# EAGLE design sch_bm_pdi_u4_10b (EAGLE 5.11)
AUTHOR: Nigel Batten; DATE: 10th May 2012; PRODUCT: PDIMate XMegaA4U BMP001U4; RANGE: BreadMate; VERSION: Sch1.0b
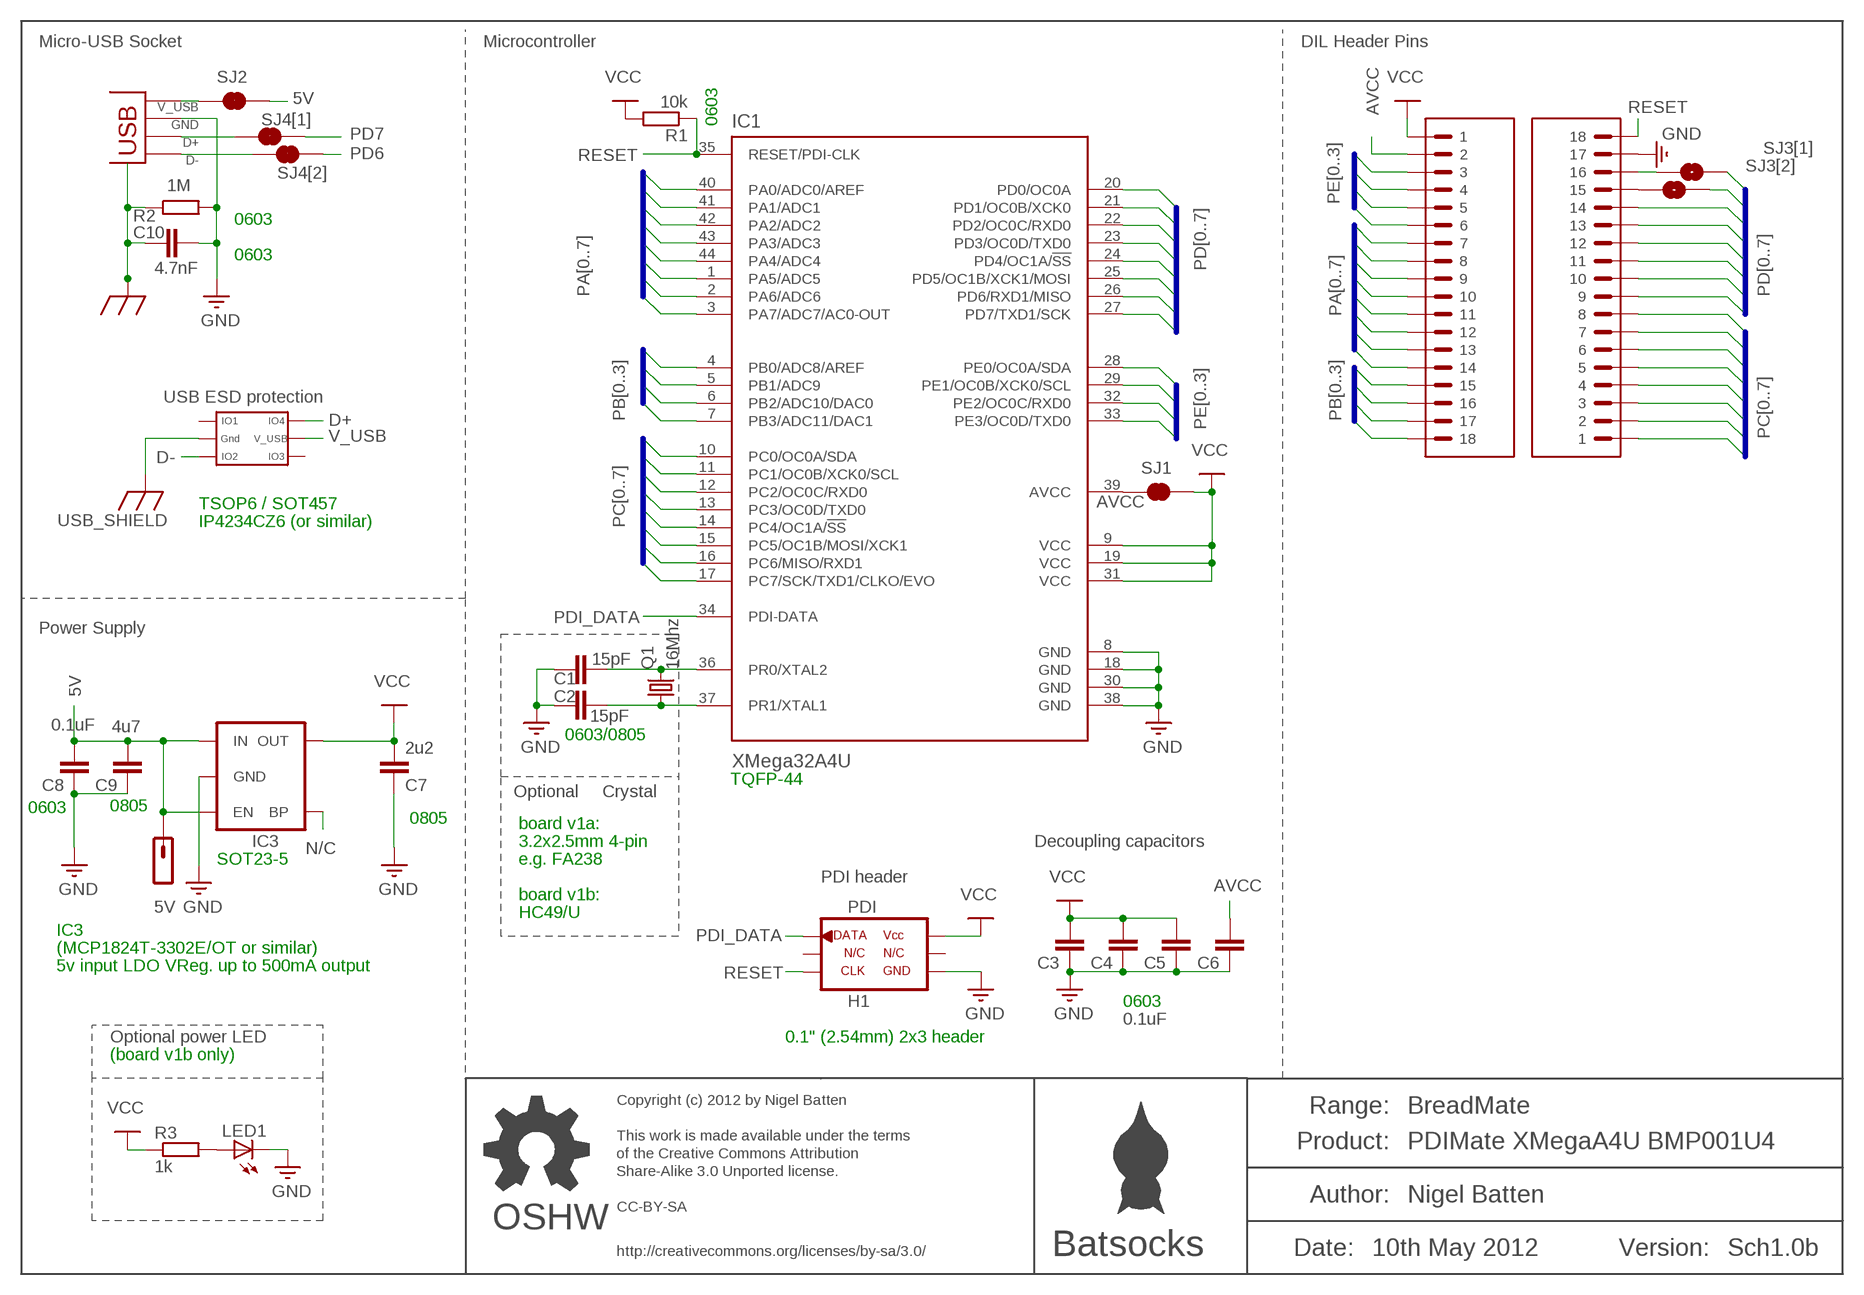
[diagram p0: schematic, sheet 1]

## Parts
5V  M01TEST  [TEST_PAD_1]
C1  15pF  C_EU0805UNMARK  [C0805U]
C2  15pF  C_EU0805UNMARK  [C0805U]
C3  0.1uF  C_EU0603  [C0603]
C4  0.1uF  C_EU0603MARK  [C0603M]
C5  0.1uF  C_EU0603MARK  [C0603M]
C6  0.1uF  C_EU0603MARK  [C0603M]
C7  2u2  C_EU0805MARK  [C0805M]
C8  0.1uF  C_EU0603MARK  [C0603M]
C9  4u7  C_EU0805MARK  [C0805M]
C10  4.7nF  C_EU0603MARK  [C0603M]
H1  PDI  AVR_PDI_6  [AVR_ISP_6]
IC1  XMega32A4U  AT-XMEGA-XXA4-AUMEDIUM  [TQFP44_M]
IC2  USB_ESD  [SOT457]
IC3  LDO  V_REG_LDOSMD  [SOT23-5]
LED1  LED0603_DIODE  [0603_DIODE]
Q1  16Mhz  CRYSTALU  [HC49/S_U]
R1  10k  RESISTOR0603MARK  [R0603M]
R2  1M  RESISTOR0603MARK  [R0603M]
R3  1k  RESISTOR0603UNMARKED  [R0603U]
SJ1  SOLDERJUMPER_NC  [SJ_NC]
SJ2  SOLDERJUMPER_NC  [SJ_NC]
SJ3[1]  SOLDERJUMPER_NOSMALL_UNMARKED  [SJ_NO_SMALL_U]
SJ3[2]  SOLDERJUMPER_NOSMALL_UNMARKED  [SJ_NO_SMALL_U]
SJ4[1]  SOLDERJUMPER_NCSMALL_UNMARKED  [SJ_NC_SMALL_U]
SJ4[2]  SOLDERJUMPER_NCSMALL_UNMARKED  [SJ_NC_SMALL_U]
U$2  HEADER_18BIGPADS_UNMARKED  [HEADER_18_BIGPADS_UNMARKED]
U$3  HEADER_18BIGPADS_UNMARKED  [HEADER_18_BIGPADS_UNMARKED]
U$4  LOGO_BATSOCKSTINY  [LOGO_BATSOCKS_TINY]
U$5  LOGO_OSHWTINY  [LOGO_OSHW_TINY]
USB_SKT  USB_SHIELD_8  [USB_MICRO_B]

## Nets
5V: 5V.P$1 C8.2 C9.2 IC3.1(IN) IC3.3(EN) SJ2.2
AVCC: C6.2 IC1.39(AVCC) SJ1.2 U$2.P$2
D+: IC2.P$6(IO4) SJ4[1].1 USB_SKT.D+
D-: IC2.P$3(IO2) SJ4[2].1 USB_SKT.D-
GND: C1.2 C2.2 C3.1 C4.1 C5.1 C6.1 C7.2 C8.1 C9.1 C10.1 H1.P$6(GND) IC1.8(GND) IC1.18(GND) IC1.30(GND) IC1.38(GND) IC3.2(GND) LED1.K(C) R2.2 U$3.P$17 USB_SKT.GND
N$1: C2.1 IC1.37(PR1/XTAL1) Q1.1
N$2: C1.1 IC1.36(PR0/XTAL2) Q1.2
N$3: SJ3[2].1 U$3.P$15
N$4: SJ3[1].1 U$3.P$16
N$5: LED1.A R3.2
N/C: IC3.4(BP)
PA0: IC1.40(PA0/ADC0/AREF) U$2.P$7
PA1: IC1.41(PA1/ADC1) U$2.P$8
PA2: IC1.42(PA2/ADC2) U$2.P$9
PA3: IC1.43(PA3/ADC3) U$2.P$10
PA4: IC1.44(PA4/ADC4) U$2.P$11
PA5: IC1.1(PA5/ADC5) U$2.P$12
PA6: IC1.2(PA6/ADC6) U$2.P$13
PA7: IC1.3(PA7/ADC7/AC0-OUT) U$2.P$14
PB0: IC1.4(PB0/ADC8/AREF) U$2.P$15
PB1: IC1.5(PB1/ADC9) U$2.P$16
PB2: IC1.6(PB2/ADC10/DAC0) U$2.P$17
PB3: IC1.7(PB3/ADC11/DAC1) U$2.P$18
PC0: IC1.10(PC0/OC0A/SDA) U$3.P$1
PC1: IC1.11(PC1/OC0B/XCK0/SCL) U$3.P$2
PC2: IC1.12(PC2/OC0C/RXD0) U$3.P$3
PC3: IC1.13(PC3/OC0D/TXD0) U$3.P$4
PC4: IC1.14(PC4/OC1A/!SS) U$3.P$5
PC5: IC1.15(PC5/OC1B/MOSI/XCK1) U$3.P$6
PC6: IC1.16(PC6/MISO/RXD1) U$3.P$7
PC7: IC1.17(PC7/SCK/TXD1/CLKO/EVO) U$3.P$8
PD0: IC1.20(PD0/OC0A) U$3.P$9
PD1: IC1.21(PD1/OC0B/XCK0) U$3.P$10
PD2: IC1.22(PD2/OC0C/RXD0) U$3.P$11
PD3: IC1.23(PD3/OC0D/TXD0) U$3.P$12
PD4: IC1.24(PD4/OC1A/!SS) U$3.P$13
PD5: IC1.25(PD5/OC1B/XCK1/MOSI) U$3.P$14
PD6: IC1.26(PD6/RXD1/MISO) SJ3[2].2 SJ4[2].2
PD7: IC1.27(PD7/TXD1/SCK) SJ3[1].2 SJ4[1].2
PDI_DATA: H1.P$1(DATA) IC1.34(PDI-DATA)
PE0: IC1.28(PE0/OC0A/SDA) U$2.P$3
PE1: IC1.29(PE1/OC0B/XCK0/SCL) U$2.P$4
PE2: IC1.32(PE2/OC0C/RXD0) U$2.P$5
PE3: IC1.33(PE3/OC0D/TXD0) U$2.P$6
RESET: H1.P$5(CLK) IC1.35(RESET/PDI-CLK) R1.1 U$3.P$18
USB_SHIELD: C10.2 IC2.P$2(GND) R2.1 USB_SKT.SHIELD$1 USB_SKT.SHIELD$2(SHIELD$1) USB_SKT.SHIELD$3(SHIELD$1) USB_SKT.SHIELD$4(SHIELD$1) USB_SKT.SHIELD$5(SHIELD$1) USB_SKT.SHIELD$6(SHIELD$1) USB_SKT.SHIELD$7(SHIELD$1) USB_SKT.SHIELD$8(SHIELD$1) ; supply symbol labelled SHIELD
V_USB: IC2.P$5(V_USB) SJ2.1 USB_SKT.VBUS(V_USB)
VCC: C3.2 C4.2 C5.2 C7.1 H1.P$2(VCC_IO) IC1.9(VCC) IC1.19(VCC) IC1.31(VCC) IC3.5(OUT) R1.2 R3.1 SJ1.1 U$2.P$1
Unconnected: H1.P$3(NC1) H1.P$4(NC2) IC2.P$1(IO1) IC2.P$4(IO3)

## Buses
PA[0..7]
PC[0..7]
PB[0..3]
PE[0..3]
PD[0..7]

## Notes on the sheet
- Micro-USB Socket | Microcontroller | DIL Header Pins
- 0603
- 0603
- 0603
- USB ESD protection
- TSOP6 / SOT457
- IP4234CZ6 (or similar)
- Power Supply
- 0603/0805
- TQFP-44
- Optional | Crystal
- 0603 | 0805 | 0805
- board v1a:
- 3.2x2.5mm 4-pin | Decoupling capacitors
- SOT23-5 | e.g. FA238
- PDI header
- board v1b:
- HC49/U
- IC3
- (MCP1824T-3302E/OT or similar)
- 5v input LDO VReg. up to 500mA output
- 0603
- Optional power LED | 0.1" (2.54mm) 2x3 header
- (board v1b only)
- Copyright (c) 2012 by Nigel Batten
- This work is made available under the terms
- of the Creative Commons Attribution
- Share-Alike 3.0 Unported license.
- CC-BY-SA
- OSHW
- http://creativecommons.org/licenses/by-sa/3.0/

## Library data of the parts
5V = Batten:M01: Header 1
C1-C10 = Batten:C_EU
H1 = Batten:AVR_PDI_6
IC1 = Batten:AT-XMEGA-XXA4-AU: ATxMega a4 Series
IC2 = Batten:USB_ESD
IC3 = Batten:V_REG_LDO: Voltage Regulator LDO Standard 150mA LDO voltage regulator in SOT-23 layout. Micrel part MIC5205. BP (by-pass) pin is used to lower output noise with 470pF cap.
LED1 = Batten:LED: LED
Q1 = Batten:CRYSTAL: Two Pin Crystal
R1-R3 = Batten:RESISTOR
SJ1 SJ2 SJ4[1] SJ4[2] = Batten:SOLDERJUMPER_NC: Solder Jumper
SJ3[1] SJ3[2] = Batten:SOLDERJUMPER_NO: Solder Jumper
U$2 U$3 = Batten:HEADER_18
U$4 = Batten:LOGO_BATSOCKS
U$5 = Batten:LOGO_OSHW
USB_SKT = Batten:USB_SHIELD_8

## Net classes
1 power: width 0.406 mm, drill 0.35 mm, clearance 0.203 mm

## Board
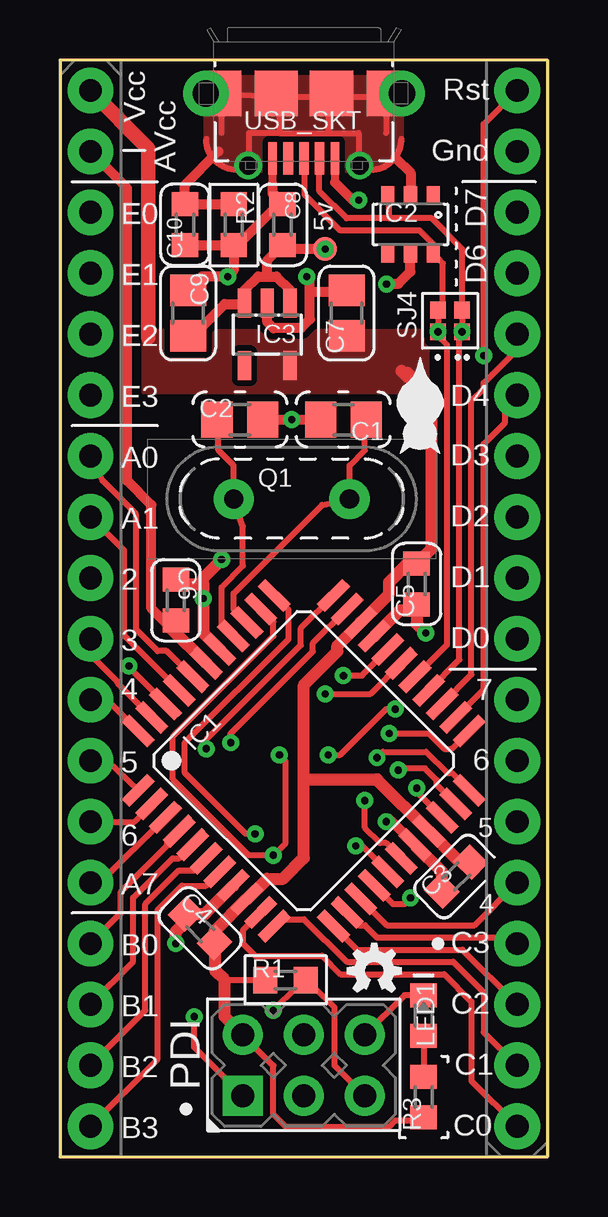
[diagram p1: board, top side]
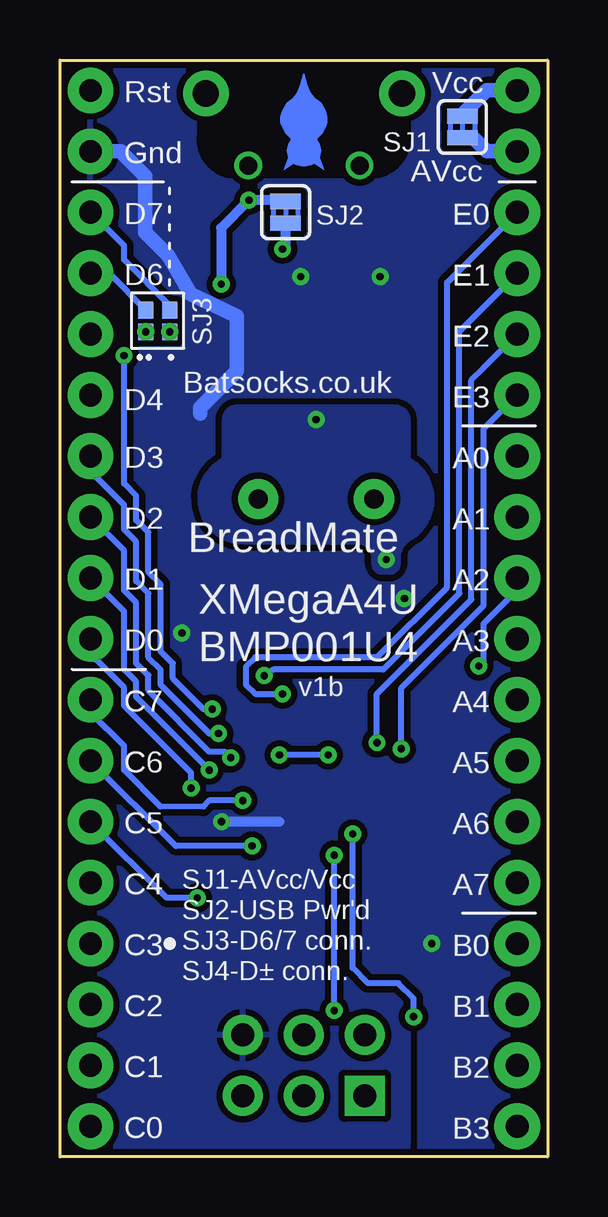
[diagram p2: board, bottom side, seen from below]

Size 20.32 x 45.72 mm. Coordinates in mm from the lower left corner, seen from the top.
Outline: 0,0 20.32,0 20.32,45.72 0,45.72 0,0
Copper layers (1*16): Top 0.035mm / dielectric 1.5mm / Bottom 0.035mm
Design rules "ITead_rule *": minimum track width 8mil, minimum drill 0.3mm, track to track 10mil, track to pad 9.5mil, pad to pad 9.5mil, via to via 10mil, smd to smd 9.5mil, copper to edge 10mil, drill to drill 10mil, minimum pad ring 8mil, minimum via ring 8mil, stop-mask expansion 4mil, vias tented up to drill 0.35mm, thermal gap 10mil
bRestrict: 20 lines

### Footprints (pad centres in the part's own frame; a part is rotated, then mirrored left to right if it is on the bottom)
TEST_PAD_1 = smd 1 x 1: P$1 0,0
C0805U = smd 1.3 x 1.5: 1 -0.95,0; 2 0.95,0
C0603 = smd 1 x 1.1: 1 -0.85,0; 2 0.85,0
C0603M = smd 1 x 1.1: 1 -0.85,0; 2 0.85,0
C0805M = smd 1.3 x 1.5: 1 -0.95,0; 2 0.95,0
AVR_ISP_6 = drill 0.95 pad 1.676 square: P$1 -1.27,2.54 | drill 0.95 pad 1.676 round: P$2 1.27,2.54; P$3 -1.27,0; P$4 1.27,0; P$5 -1.27,-2.54; P$6 1.27,-2.54
TQFP44_M = smd 1.5 x 0.45: 1 -5.75,4; 2 -5.75,3.2; 3 -5.75,2.4; 4 -5.75,1.6; 5 -5.75,0.8; 6 -5.75,0; 7 -5.75,-0.8; 8 -5.75,-1.6; 9 -5.75,-2.4; 10 -5.75,-3.2; 11 -5.75,-4; 23 5.75,-4; 24 5.75,-3.2; 25 5.75,-2.4; 26 5.75,-1.6; 27 5.75,-0.8; 28 5.75,0; 29 5.75,0.8; 30 5.75,1.6; 31 5.75,2.4; 32 5.75,3.2; 33 5.75,4 | smd 0.45 x 1.5: 12 -4,-5.75; 13 -3.2,-5.75; 14 -2.4,-5.75; 15 -1.6,-5.75; 16 -0.8,-5.75; 17 0,-5.75; 18 0.8,-5.75; 19 1.6,-5.75; 20 2.4,-5.75; 21 3.2,-5.75; 22 4,-5.75; 34 4,5.75; 35 3.2,5.75; 36 2.4,5.75; 37 1.6,5.75; 38 0.8,5.75; 39 0,5.75; 40 -0.8,5.75; 41 -1.6,5.75; 42 -2.4,5.75; 43 -3.2,5.75; 44 -4,5.75
SOT457 = smd 0.8 x 0.55: P$1 -1.2,0.95; P$2 -1.2,0; P$3 -1.2,-0.95; P$4 1.2,-0.95; P$5 1.2,0; P$6 1.2,0.95
SOT23-5 = smd 0.55 x 1.2: 1 -0.95,-1.3; 2 0,-1.3; 3 0.95,-1.3; 4 0.95,1.3; 5 -0.95,1.3
0603_DIODE = smd 1 x 1.1: A 0.85,0; K -0.85,0
HC49/S_U = drill 0.8 pad 1.676 round: 1 -2.413,0; 2 2.413,0
R0603M = smd 1 x 1.1: 1 -0.85,0; 2 0.85,0
R0603U = smd 1 x 1.1: 1 -0.85,0; 2 0.85,0
SJ_NC = smd 0.635 x 1.27: 1 -0.45,0; 2 0.45,0
SJ_NO_SMALL_U = smd 0.7 x 0.635: 1 -0.45,0; 2 0.45,0
SJ_NC_SMALL_U = smd 0.7 x 0.635: 1 -0.45,0; 2 0.45,0
HEADER_18_BIGPADS_UNMARKED = drill 0.95 pad 1.905 round: P$1 -21.59,0; P$2 -19.05,0; P$3 -16.51,0; P$4 -13.97,0; P$5 -11.43,0; P$6 -8.89,0; P$7 -6.35,0; P$8 -3.81,0; P$9 -1.27,0; P$10 1.27,0; P$11 3.81,0; P$12 6.35,0; P$13 8.89,0; P$14 11.43,0; P$15 13.97,0; P$16 16.51,0; P$17 19.05,0; P$18 21.59,0
USB_MICRO_B = smd 0.4 x 1.35: D+ 0,-2.7; D- 0.65,-2.7; ID -0.65,-2.7 | smd 0.35 x 1.35: GND -1.3,-2.7; VBUS 1.3,-2.7 | drill 1.1 pad 1.9 round: SHIELD$1 -4.085,0; SHIELD$2 4.085,0 | drill 0.75 pad 1.15 round: SHIELD$3 -2.32,-3; SHIELD$4 2.32,-3 | smd 1.47 x 1.9: SHIELD$5 -3.35,0; SHIELD$8 3.35,0 | smd 1.8 x 1.9: SHIELD$6 -1.15,0; SHIELD$7 1.15,0

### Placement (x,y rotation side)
5V  11.05,37.84 0 top
C1  11.81,30.72 180 top
C2  7.49,30.72 0 top
C3  16.51,11.68 45 top
C4  5.84,9.53 315 top
C5  14.86,23.88 90 top
C6  4.83,23.2 270 top
C7  11.94,35.17 90 top
C8  9.27,38.85 270 top
C9  5.33,35.17 270 top
C10  5.21,38.85 90 top
H1  10.16,3.81 90 top
IC1  10.16,16.51 45 top
IC2  14.61,38.86 270 top
IC3  8.64,34.28 180 top
LED1  15.15,5.89 270 top
Q1  9.65,27.42 0 top
R1  9.4,7.37 180 top
R2  7.24,38.85 270 top
R3  15.15,2.49 90 top
SJ1  3.56,42.93 270 bottom
SJ2  10.92,39.37 270 bottom
SJ3[1]  15.75,34.84 270 bottom
SJ3[2]  16.75,34.84 270 bottom
SJ4[1]  15.75,34.84 270 top
SJ4[2]  16.75,34.84 270 top
U$2  1.27,22.86 270 top
U$3  19.05,22.86 90 top
U$4  15.01,31.36 0 top
U$5  13.1,7.75 0 top
U$6  [LOGO_BATSOCKS_COPPER_TINY]  10.16,43.17 0 bottom
USB_SKT  10.16,44.32 0 top

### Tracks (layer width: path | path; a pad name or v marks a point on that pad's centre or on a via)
5V  (via drill 0.3)
  Top 0.406: 5V.P$1 11.18,37.85 9.17,37.85 C8.2 8.64,37.37 8.64,36.69 | C9.2 5.33,34.28 5.59,34.28 6.86,35.55 7.66,35.55 IC3.3 7.69,36.12 8.26,36.69 8.64,36.69 | 8.64,36.69 9.02,36.69 9.59,36.12 IC3.1
  Bottom 0.406: SJ2.2 10.92,37.97 5V.P$1
  other vias: 11.05,37.84
AVCC
  Top 0.406: U$2.P$2 2.79,40.38 2.79,28.18 3.81,27.17 3.81,22.86 4.57,22.09
  Top 0.508: IC1.39 4.57,22.09 C6.2
  Bottom 0.406: 3.05,42.42 3.11,42.48 SJ1.2
  Bottom 0.61: U$2.P$2 2.54,41.91 3.05,42.42
D+
  Top 0.254: USB_SKT.D+ 10.2,41.49 10.2,40.08 10.21,40.08 11.68,38.61 14.99,38.61 15.55,38.04 IC2.P$6 15.95,37.24 15.95,35.49 SJ4[1].1
D-
  Top 0.254: 13.72,39.12 15.49,39.12 16.75,37.84 SJ4[2].1 | 13.72,39.12 11.94,39.12 10.81,40.24 USB_SKT.D- | IC2.P$3 13.65,39.94 13.72,39.88 13.72,39.12
GND  (via drill 0.3)
  Top 0.254: LED1.K 14.36,6.74 H1.P$6
  Top 0.33: 8.86,40.54 USB_SKT.GND
  Top 0.406: v13.59,13.97 13.7,14.1 IC1.18 | 8.86,40.54 8.86,40.16 9.14,39.88 9.14,39.83 C8.1 | C8.1 8.96,39.69 | IC3.2 8.64,34.79 8.89,34.53 10.03,34.53 10.41,34.91 10.41,36.06 | 10.41,36.06 10.41,36.57 v10.29,36.69 | C10.1 R2.2 | R2.2 7.24,36.95 v6.99,36.69 5.91,36.69 C9.1 | R2.2 7.41,38 9.11,39.7 C8.1 | C7.2 11.94,36.06 10.41,36.06 | C2.2 8.45,30.73 v9.65,30.73 10.85,30.73 C1.2
  Top 0.508: IC1.38 5.97,21.83 v5.97,23.27 5.97,23.87 | C3.1 15.91,11.89 IC1.18 | IC1.8 6.04,10.13 C4.1 5.33,10.03 5.33,9.91 4.83,9.4 v4.83,8.89 | v6.73,24.89 5.97,24.13 5.97,23.87 | 5.97,23.87 4.91,23.87 C6.1 | IC1.30 14.18,22.79 14.6,22.79 14.84,23.03 C5.1 14.86,22.21 v15.24,21.83
  Bottom 0.406: 11.18,13.97 v13.59,13.97
  Bottom 0.61: U$3.P$17 17.78,41.91 17.78,41.9 16.76,40.88 16.76,38.52 15.8,37.56 14.86,35.96 12.95,35.04 12.95,32.76 14.48,31.23 14.48,30.99
  pour Bottom (rank 3): 0,45.72 5.59,45.72 5.59,42.42 arc90 7.37,40.64 13.21,40.64 arc90 14.73,42.67 14.73,45.72 20.32,45.72 20.32,0 0,0
N$1
  Top 0.254: IC1.37 6.73,22.2 6.73,23.75 7.62,24.64 7.62,26.28 Q1.1 7.24,28.82 6.6,29.45 6.6,30.66 C2.1
N$2
  Top 0.254: IC1.36 7.24,22.82 7.24,23.48 10.92,27.17 Q1.2 12.06,28.82 12.7,29.45 12.7,30.66 C1.1
N$3
  Bottom 0.254: SJ3[2].1 18.26,36.84 U$3.P$15
N$4
  Bottom 0.254: SJ3[1].1 15.75,35.49 17.65,37.4 17.65,37.97 U$3.P$16
N$5
  Top 0.254: LED1.A R3.2
PA0
  Top 0.254: U$2.P$7 1.78,28.18 3.17,26.79 3.17,21.97 4.06,21.08 4.46,21.08 IC1.40
PA1
  Top 0.254: U$2.P$8 2.67,25.27 2.67,21.74 IC1.41
PA2  (via drill 0.3)
  Top 0.254: v2.88,20.46 2.92,20.36 IC1.42
  Bottom 0.254: U$2.P$9 1.27,23.62 2.67,22.22 2.67,20.66 v2.88,20.46
PA3
  Top 0.254: U$2.P$10 1.27,20.94 2.41,19.8 2.41,19.73 IC1.43
PA4
  Top 0.254: U$2.P$11 1.96,19.05 IC1.44
PA5
  Top 0.254: U$2.P$12 1.96,16.51 IC1.1
PA6
  Top 0.254: U$2.P$13 3.1,13.97 IC1.2
PA7
  Top 0.254: U$2.P$14 1.69,11.43 IC1.3
PB0
  Top 0.254: U$2.P$15 2.54,10.16 2.54,11.05 4.57,13.08 4.47,13.08 IC1.4
PB1
  Top 0.254: U$2.P$16 3.05,8.13 3.05,10.79 4.7,12.45 4.96,12.45 IC1.5
PB2
  Top 0.254: U$2.P$17 3.56,6.1 3.56,10.54 4.95,11.94 5.59,11.94 IC1.6
PB3
  Top 0.254: U$2.P$18 4.06,4.06 4.06,10.29 5.08,11.3 6.08,11.3 IC1.7
PC0
  Top 0.254: U$3.P$1 17.14,3.17 17.14,6.47 16,7.61 11.68,7.61 10.92,8.38 8.13,8.38 7.62,8.89 7.62,9.44 IC1.10
PC1
  Top 0.254: U$3.P$2 17.65,5.2 17.65,6.85 16.38,8.13 11.94,8.13 10.16,9.91 9.21,9.91 IC1.11
PC2
  Top 0.254: U$3.P$3 16.76,8.64 12.38,8.64 IC1.12
PC3
  Top 0.254: U$3.P$4 18.8,9.14 13.21,9.14 12.7,9.65 12.45,9.65 12.45,9.7 IC1.13
PC4
  Top 0.254: U$3.P$5 17.27,9.65 13.62,9.65 IC1.14
PC5  (via drill 0.3)
  Top 0.254: v14.61,10.79 14.35,10.54 13.87,10.54 IC1.15
  Bottom 0.254: U$3.P$6 15.88,10.79 v14.61,10.79
PC6  (via drill 0.3)
  Top 0.254: v12.32,12.95 12.59,12.95 IC1.16
  Bottom 0.254: U$3.P$7 15.49,12.95 v12.32,12.95
PC7  (via drill 0.3)
  Top 0.254: v12.7,14.85 12.7,13.72 13.34,13.08 13.59,13.08 IC1.17
  Bottom 0.254: U$3.P$8 19.05,18.53 17.65,17.13 17.65,16.12 16.14,14.61 14.35,14.6 14.1,14.85 v12.7,14.85
PD0  (via drill 0.3)
  Top 0.254: v14.86,15.37 14.86,15.21 IC1.20
  Bottom 0.254: v14.86,15.37 14.86,16 17.65,18.8 17.65,19.56 18.8,20.7 18.8,21.34 U$3.P$9
PD1  (via drill 0.3)
  Top 0.254: v14.1,16.12 14.13,16.12 14.2,16.19 15.2,16.19 15.7,15.69 15.7,15.5 IC1.21
  Bottom 0.254: v14.1,16.12 17.14,19.18 17.14,19.81 17.65,20.32 17.65,22.73 U$3.P$10
PD2  (via drill 0.3)
  Top 0.254: v13.21,16.64 13.46,16.88 15.24,16.88 16.13,15.99 16.34,15.99 IC1.22
  Bottom 0.254: v13.21,16.64 13.21,16.63 13.46,16.88 14.1,16.88 16.64,19.43 16.64,20.07 17.14,20.57 17.14,23.1 17.65,23.61 17.65,25.26 U$3.P$11
PD3  (via drill 0.3)
  Top 0.254: v13.72,17.64 15.37,17.64 16,17.01 16.32,17.01 IC1.23
  Bottom 0.254: U$3.P$12 18.8,28.31 17.65,27.17 17.65,26.15 17.14,25.64 17.14,23.99 16.64,23.48 16.64,20.82 16.13,20.31 16.13,19.67 14.1,17.64 v13.72,17.64
PD4
  Top 0.254: U$3.P$13 19.05,31.5 18.54,30.99 18.54,30.61 17.65,29.72 17.65,19.48 IC1.24
PD5
  Top 0.254: U$3.P$14 19.05,33.66 17.65,32.26 17.65,32.01 17.14,31.5 17.14,20.1 IC1.25
PD6  (via drill 0.3)
  Top 0.254: IC1.26 16.64,20.72 16.64,34.3 16.73,34.42 SJ3[2].2
  other vias: 16.75,34.39
PD7  (via drill 0.3)
  Top 0.254: SJ3[1].2 15.75,34.23 16.13,33.85 16.13,21.35 IC1.27
  other vias: 15.75,34.39
PDI_DATA  (via drill 0.3)
  Top 0.254: H1.P$1 5.59,4.57 v5.59,5.84 | v8.13,13.46 7.74,13.46 5.21,15.99 5.21,17.26 9.53,21.58 9.53,22.8 IC1.34
  Bottom 0.254: v5.59,5.84 5.59,6.6 6.22,7.24 7.49,7.24 8.13,7.87 v8.13,13.46
PE0  (via drill 0.3)
  Top 0.254: v11.05,19.29 12.94,19.29 IC1.28
  Bottom 0.254: U$2.P$3 4.19,36.44 4.19,23.74 7.11,20.82 12.19,20.82 12.57,20.44 12.57,19.67 12.19,19.29 v11.05,19.29
PE1  (via drill 0.3)
  Top 0.254: v11.81,20.06 12.57,20.06 IC1.29
  Bottom 0.254: U$2.P$4 3.68,34.41 3.68,23.48 6.86,20.31 11.43,20.31 v11.81,20.06
PE2  (via drill 0.3)
  Top 0.254: v7.11,17.26 7.11,17.64 10.54,21.07 10.54,21.42 IC1.32
  Bottom 0.254: U$2.P$5 2.67,32.89 2.67,32.88 3.17,32.38 3.17,23.23 7.11,19.29 v7.11,17.26
PE3  (via drill 0.3)
  Top 0.254: v6.1,17.01 6.1,17.39 10.03,21.33 10.03,22.04 IC1.33
  Bottom 0.254: U$2.P$6 2.67,30.35 2.67,22.98 6.1,19.55 v6.1,17.01
RESET  (via drill 0.3)
  Top 0.254: 8.36,22.88 IC1.35 8.89,22.3 8.89,21.71 4.7,17.52 4.7,15.74 7.86,12.57 v8.89,12.57 v8.9,12.57 9.4,13.07 9.4,16.5 v9.14,16.75 | H1.P$5 11.43,3.81 11.43,6.22 10.54,7.11 R1.1 9.99,7.11 9.91,7.11 v8.89,6.1 | v17.65,33.4 17.65,43.05 U$3.P$18 | v11.18,16.75 11.68,16.75 13.59,18.66 v13.97,18.66
  Bottom 0.254: v8.89,6.1 v8.89,12.57 | v17.65,33.4 17.65,28.06 17.14,27.55 17.14,26.53 16.65,26.04 16.64,26.04 16.64,24.37 16.13,23.87 16.13,21.07 15.62,20.56 15.62,19.93 14.35,18.66 v13.97,18.66 | v9.14,16.75 v11.18,16.75
USB_SHIELD
  Top 0.254: 6.1,42.42 arc90 7.37,41.15 7.87,41.15 7.87,42.67 9.14,42.67 | 9.14,42.67 11.18,42.67 | 11.18,42.67 12.45,42.67 12.45,41.15 12.95,41.15 arc53 13.97,41.66 arc37 14.22,42.42 | 9.14,44.2 USB_SKT.SHIELD$5 6.73,44.2 | 9.14,44.2 11.18,44.2 | 11.18,44.2 13.59,44.2 | 13.59,44.2 14.22,44.2 | 9.14,44.2 9.14,42.67 | 11.18,44.2 11.18,42.67 | 13.59,44.2 13.59,42.67 | 6.73,42.67 6.73,44.2 | 6.73,44.2 USB_SKT.SHIELD$1
  Top 0.406: 13.97,41.66 14.61,41.02 IC2.P$2 | 6.6,41.91 5.21,40.5 C10.2 R2.1
  pour Top (isolate 0.254, no thermals): 6.1,44.96 6.1,42.42 arc90 7.37,41.15 12.95,41.15 arc90 14.22,42.42 14.22,44.96
V_USB  (via drill 0.3)
  Top 0.33: 11.46,40.61 USB_SKT.VBUS
  Top 0.406: v12.45,39.88 12.19,39.88 11.46,40.61 | v13.61,36.38 v13.6,36.39 14.1,36.39 14.6,36.89 IC2.P$5
  Bottom 0.406: SJ2.1 10.92,39.88 v12.45,39.88 13.61,38.72 v13.61,36.38
VCC
  Top 0.254: 6.86,7.37 R1.2 | H1.P$2 8.89,3.8 8.89,1.77 9.4,1.26 13.72,1.26 13.97,1.51 15.02,1.51 R3.1
  Top 0.508: H1.P$2 6.86,5.84 6.86,7.37 6.48,7.75 6.48,8.83 C4.2 6.44,9.4 IC1.9 8.63,11.59 9.3,11.59 10.16,12.45 10.16,15.74 | C3.2 16.52,12.41 IC1.19 13.21,15.74 10.16,15.74 | 14.22,32.76 14.48,32.5 14.48,32.68 15.49,31.66 15.49,25.36 C5.2 14.49,24.73 13.72,23.95 13.72,23.46 IC1.31 11.56,21.3 11.56,21.07 10.16,19.67 10.16,15.74
  Top 0.61: U$2.P$1 3.68,42.03 3.68,34.15
  Bottom 0.61: U$2.P$1 2.54,44.45 3.56,43.43 SJ1.1
  pour Top (no thermals): 3.53,34.39 15.25,34.39 15.25,31.89 3.53,31.89

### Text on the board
tPlace: Rst | Vcc | Gnd | AVcc | E0 | 5v | D7 | E1 | SJ4 | D6 | E2 | D4 | E3 | D3 | A0 | D2 | A1 | D1 | 2 | D0 | 3 | 7 | 4 | 6 | 5 | 5 | 6 | A7 | 4 | C3 | B0 | C2 | B1 | C1 | B2 | PDI | C0 | B3
bPlace: Vcc | Rst | SJ1 | AVcc | Gnd | E0 | SJ2 | D7 | E1 | D6 | E2 | SJ3 | E3 | Batsocks.co.uk | D4 | A0 | D3 | A1 | D2 | A2 | BreadMate | D1 | XMegaA4U | A3 | BMP001U4 | D0 | A4 | v1b | C7 | A5 | C6 | A6 | C5 | A7 | SJ1-AVcc/Vcc | C4 | SJ2-USB Pwr'd | B0 | SJ3-D6/7 conn. | C3 | B1 | SJ4-D± conn. | C2 | B2 | C1 | B3 | C0
tValues: 3.3v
